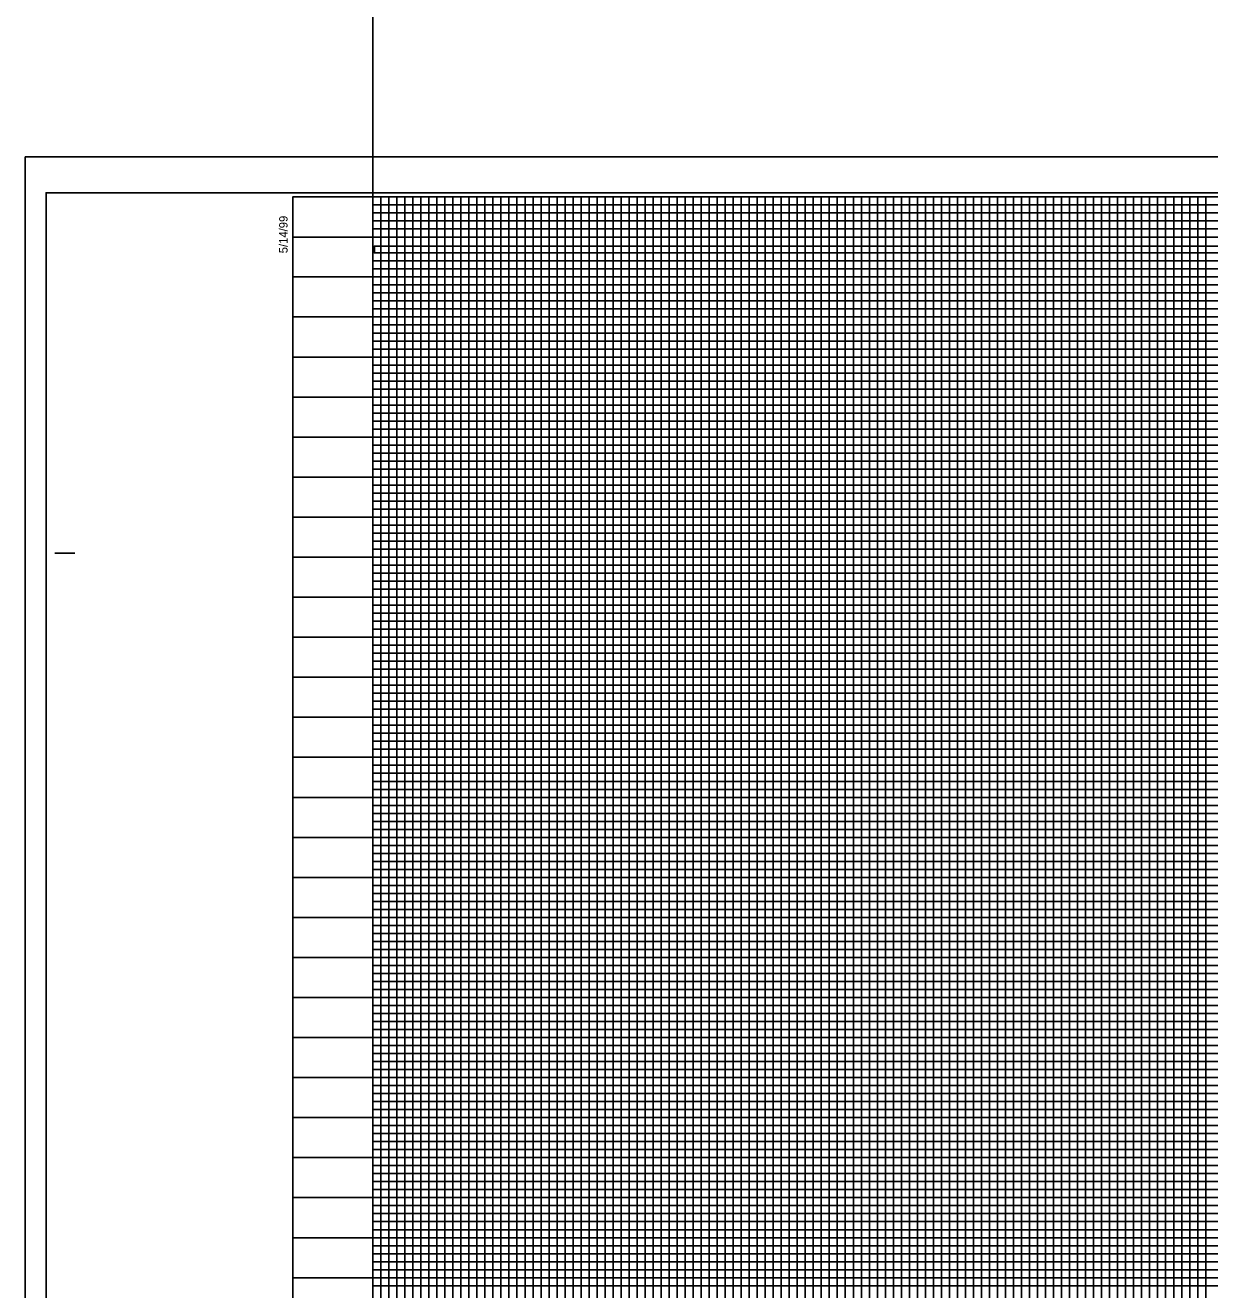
# Model space of a CAD drawing. Extents: x 2345490 to 2445302, y 465165 to 573888.
# Drawn here: x 2381550 to 2382289, y 510797 to 511587 of the extents above; entities that cross this region are included whole.
import ezdxf

# ---------------------------------------------------------------- set-up
doc = ezdxf.new("R2010")
doc.units = 0
for name, color, linetype in [('Old_Level_18', 7, 'Continuous'), ('Old_Level_41', 7, 'Continuous'), ('Old_Level_42', 7, 'Continuous'), ('Old_Level_43', 7, 'Continuous'), ('Old_Level_50', 7, 'Continuous'), ('Old_Level_51', 7, 'Continuous'), ('Old_Level_63', 7, 'Continuous')]:
    doc.layers.add(name, color=color, linetype=linetype)

msp = doc.modelspace()

# ---------------------------------------------------------------- linework, layer by layer
at = {"layer": 'Old_Level_18'}
msp.add_lwpolyline([(2383216.79875, 511479.3835), (2381716.79875, 511479.3835), (2381716.79875, 510429.3835), (2383216.79875, 510429.3835)], close=True, dxfattribs=at)
at = {"layer": 'Old_Level_41'}
msp.add_line((2381568.29875, 511256.8835), (2381580.79875, 511256.8835), dxfattribs=at)
for points in [[(2381716.79875, 511479.3835), (2381766.79875, 511479.3835), (2381766.79875, 510454.3835)], [(2381791.79875, 510454.3835), (2381791.79875, 511479.3835), (2381841.79875, 511479.3835), (2381841.79875, 510454.3835)], [(2381816.79875, 510454.3835), (2381816.79875, 511479.3835), (2381866.79875, 511479.3835), (2381866.79875, 510454.3835)], [(2381891.79875, 510454.3835), (2381891.79875, 511479.3835), (2381941.79875, 511479.3835), (2381941.79875, 510454.3835)], [(2381916.79875, 510454.3835), (2381916.79875, 511479.3835), (2381966.79875, 511479.3835), (2381966.79875, 510454.3835)], [(2381991.79875, 510454.3835), (2381991.79875, 511479.3835), (2382041.79875, 511479.3835), (2382041.79875, 510454.3835)], [(2382016.79875, 510454.3835), (2382016.79875, 511479.3835), (2382066.79875, 511479.3835), (2382066.79875, 510454.3835)], [(2382091.79875, 510454.3835), (2382091.79875, 511479.3835), (2382141.79875, 511479.3835), (2382141.79875, 510454.3835)], [(2382116.79875, 510454.3835), (2382116.79875, 511479.3835), (2382166.79875, 511479.3835), (2382166.79875, 510454.3835)], [(2382191.79875, 510454.3835), (2382191.79875, 511479.3835), (2382241.79875, 511479.3835), (2382241.79875, 510454.3835)], [(2382216.79875, 510454.3835), (2382216.79875, 511479.3835), (2382266.79875, 511479.3835), (2382266.79875, 510454.3835)], [(2381716.79875, 511429.3835), (2383016.74875, 511429.3835)], [(2383016.74875, 511379.3835), (2381716.79875, 511379.3835), (2381716.79875, 511329.3335), (2383216.79875, 511329.3335)], [(2383216.79875, 511304.3835), (2381716.79875, 511304.3835), (2381716.79875, 511354.3835), (2383016.74875, 511354.3835)], [(2383216.79875, 511279.3835), (2381716.79875, 511279.3835), (2381716.79875, 511229.3835), (2383216.79875, 511229.3835)], [(2383216.79875, 511204.3835), (2381716.79875, 511204.3835), (2381716.79875, 511254.3835), (2383216.79875, 511254.3835)], [(2383216.79875, 511179.3835), (2381716.79875, 511179.3835), (2381716.79875, 511129.3835), (2383216.79875, 511129.3835)], [(2383216.79875, 511079.3835), (2381716.79875, 511079.3835), (2381716.79875, 511029.3835), (2383216.79875, 511029.3835)], [(2383216.79875, 510979.3835), (2381716.79875, 510979.3835), (2381716.79875, 510929.3835), (2383216.79875, 510929.3835)], [(2383216.79875, 510879.3835), (2381716.79875, 510879.3835), (2381716.79875, 510829.3835), (2383216.79875, 510829.3835)], [(2383216.79875, 510804.3835), (2381716.79875, 510804.3835), (2381716.79875, 510854.3835), (2383216.79875, 510854.3835)]]:
    msp.add_lwpolyline(points, dxfattribs=at)
at = {"layer": 'Old_Level_42'}
for points in [[(2383016.74875, 511404.3835), (2381716.89875, 511404.3835), (2381716.89875, 511454.3335), (2383016.74875, 511454.3335)], [(2383216.79875, 511104.3835), (2381716.79875, 511104.3835), (2381716.79875, 511154.3835), (2383216.79875, 511154.3835)], [(2383216.79875, 511004.3835), (2381716.79875, 511004.3835), (2381716.79875, 511054.3835), (2383216.79875, 511054.3835)], [(2383216.79875, 510904.3835), (2381716.79875, 510904.3835), (2381716.79875, 510954.3835), (2383216.79875, 510954.3835)]]:
    msp.add_lwpolyline(points, dxfattribs=at)
at = {"layer": 'Old_Level_43'}
for p, q in [((2383166.79875, 511299.3835), (2381766.79875, 511299.3835)), ((2381766.79875, 511299.3835), (2381766.79875, 511294.3835)), ((2381766.79875, 511294.3835), (2383166.79875, 511294.3835)), ((2383166.79875, 511274.3835), (2381766.79875, 511274.3835))]:
    msp.add_line(p, q, dxfattribs=at)
for points in [[(2381771.79875, 511479.3835), (2381776.79875, 511479.3835), (2381781.79875, 511479.3835), (2381786.79875, 511479.3835), (2381796.79875, 511479.3835), (2381763.74875, 511479.3835), (2381768.74875, 511479.3835), (2381726.79875, 511479.3835), (2381731.79875, 511479.3835), (2381736.79875, 511479.3835), (2381746.79875, 511479.3835), (2381751.79875, 511479.3835), (2381756.79875, 511479.3835), (2381761.79875, 511479.3835), (2381771.79875, 511479.3835), (2381771.79875, 510454.3835)], [(2381776.79875, 510454.3835), (2381776.79875, 511479.3835), (2381781.79875, 511479.3835), (2381781.79875, 510454.3835)], [(2381786.79875, 510454.3835), (2381786.79875, 511479.3835), (2381796.79875, 511479.3835), (2381796.79875, 510454.3835)], [(2381801.79875, 510454.3835), (2381801.79875, 511479.3835), (2381806.79875, 511479.3835), (2381806.79875, 510454.3835)], [(2381811.79875, 510454.3835), (2381811.79875, 511479.3835), (2381821.79875, 511479.3835), (2381821.79875, 510454.3835)], [(2381826.79875, 510454.3835), (2381826.79875, 511479.3835), (2381831.79875, 511479.3835), (2381831.79875, 510454.3835)], [(2381836.79875, 510454.3835), (2381836.79875, 511479.3835), (2381846.79875, 511479.3835), (2381846.79875, 510454.3835)], [(2381851.79875, 510454.3835), (2381851.79875, 511479.3835), (2381856.79875, 511479.3835), (2381856.79875, 510454.3835)], [(2381861.79875, 510454.3835), (2381861.79875, 511479.3835), (2381871.79875, 511479.3835), (2381871.79875, 510454.3835)], [(2381876.79875, 510454.3835), (2381876.79875, 511479.3835), (2381881.79875, 511479.3835), (2381881.79875, 510454.3835)], [(2381886.79875, 510454.3835), (2381886.79875, 511479.3835), (2381896.79875, 511479.3835), (2381896.79875, 510454.3835)], [(2381901.79875, 510454.3835), (2381901.79875, 511479.3835), (2381906.79875, 511479.3835), (2381906.79875, 510454.3835)], [(2381911.79875, 510454.3835), (2381911.79875, 511479.3835), (2381921.79875, 511479.3835), (2381921.79875, 510454.3835)], [(2381926.79875, 510454.3835), (2381926.79875, 511479.3835), (2381931.79875, 511479.3835), (2381931.79875, 510454.3835)], [(2381936.79875, 510454.3835), (2381936.79875, 511479.3835), (2381946.79875, 511479.3835), (2381946.79875, 510454.3835)], [(2381951.79875, 510454.3835), (2381951.79875, 511479.3835), (2381956.79875, 511479.3835), (2381956.79875, 510454.3835)], [(2381961.79875, 510454.3835), (2381961.79875, 511479.3835), (2381971.79875, 511479.3835), (2381971.79875, 510454.3835)], [(2381976.79875, 510454.3835), (2381976.79875, 511479.3835), (2381976.79875, 511479.3835), (2381981.79875, 511479.3835), (2381981.79875, 510454.3835)], [(2381986.79875, 510454.3835), (2381986.79875, 511479.3835), (2381996.79875, 511479.3835), (2381996.79875, 510454.3835)], [(2382001.79875, 510454.3835), (2382001.79875, 511479.3835), (2382006.79875, 511479.3835), (2382006.79875, 510454.3835)], [(2382011.79875, 510454.3835), (2382011.79875, 511479.3835), (2382021.79875, 511479.3835), (2382021.79875, 510454.3835)], [(2382026.79875, 510454.3835), (2382026.79875, 511479.3835), (2382031.79875, 511479.3835), (2382031.79875, 510454.3835)], [(2382036.79875, 510454.3835), (2382036.79875, 511479.3835), (2382046.79875, 511479.3835), (2382046.79875, 510454.3835)], [(2382051.79875, 510454.3835), (2382051.79875, 511479.3835), (2382056.79875, 511479.3835), (2382056.79875, 510454.3835)], [(2382061.79875, 510454.3835), (2382061.79875, 511479.3835), (2382071.79875, 511479.3835), (2382071.79875, 510454.3835)], [(2382076.79875, 510454.3835), (2382076.79875, 511479.3835), (2382081.79875, 511479.3835), (2382081.79875, 510454.3835)], [(2382086.79875, 510454.3835), (2382086.79875, 511479.3835), (2382096.79875, 511479.3835), (2382096.79875, 510454.3835)], [(2382101.79875, 511479.3835), (2382101.79875, 510454.3835), (2382106.79875, 510454.3835), (2382106.79875, 511479.3835)], [(2382101.79875, 511478.7835), (2382101.79875, 510454.3835), (2382106.79875, 510454.3835), (2382106.79875, 511478.7835)], [(2382111.79875, 510454.3835), (2382111.79875, 511479.3835), (2382121.79875, 511479.3835), (2382121.79875, 510454.3835)], [(2382126.79875, 510454.3835), (2382126.79875, 511479.3835), (2382131.79875, 511479.3835), (2382131.79875, 510454.3835)], [(2382136.79875, 510454.3835), (2382136.79875, 511479.3835), (2382146.79875, 511479.3835), (2382146.79875, 510454.3835)], [(2382151.79875, 510454.3835), (2382151.79875, 511479.3835), (2382156.79875, 511479.3835), (2382156.79875, 510454.3835)], [(2382161.79875, 510454.3835), (2382161.79875, 511479.3835), (2382171.79875, 511479.3835), (2382171.79875, 510454.3835)], [(2382176.79875, 510454.3835), (2382176.79875, 511479.3835), (2382181.79875, 511479.3835), (2382181.79875, 510454.3835)], [(2382186.79875, 510454.3835), (2382186.79875, 511479.3835), (2382196.79875, 511479.3835), (2382196.79875, 510454.3835)], [(2382201.79875, 510454.3835), (2382201.79875, 511479.3835), (2382206.79875, 511479.3835), (2382206.79875, 510454.3835)], [(2382211.79875, 510454.3835), (2382211.79875, 511479.3835), (2382221.79875, 511479.3835), (2382221.79875, 510454.3835)], [(2382226.79875, 510454.3835), (2382226.79875, 511479.3835), (2382231.79875, 511479.3835), (2382231.79875, 510454.3835)], [(2382236.79875, 510454.3835), (2382236.79875, 511479.3835), (2382246.79875, 511479.3835), (2382246.79875, 510454.3835)], [(2382251.79875, 511479.3835), (2382251.79875, 510454.3835), (2382256.79875, 510454.3835), (2382256.79875, 511479.3835), (2382261.79875, 511479.3835), (2382261.79875, 510454.3835), (2382271.79875, 510454.3835), (2382271.79875, 511479.3835), (2382276.79875, 511479.3835), (2382276.79875, 510454.3835), (2382281.79875, 510454.3835), (2382281.79875, 511479.3835), (2382286.79875, 511479.3835), (2382286.79875, 510454.3835)], [(2383016.74875, 511474.3835), (2381766.79875, 511474.3835), (2381766.79875, 511469.3835), (2383016.74875, 511469.3835)], [(2383016.74875, 511464.3835), (2381766.79875, 511464.3835), (2381766.79875, 511459.3835), (2383016.74875, 511459.3835)], [(2383016.74875, 511448.6335), (2381767.79875, 511448.6335), (2381767.79875, 511444.3835), (2383016.74875, 511444.3835)], [(2383016.74875, 511439.3835), (2381766.79875, 511439.3835), (2381766.79875, 511434.3835), (2383016.74875, 511434.3835)], [(2383016.74875, 511424.3835), (2381766.79875, 511424.3835), (2381766.79875, 511419.3835), (2383016.74875, 511419.3835)], [(2383016.74875, 511414.3835), (2381766.79875, 511414.3835), (2381766.79875, 511409.3835), (2383016.74875, 511409.3835)], [(2383016.74875, 511399.3835), (2381766.79875, 511399.3835), (2381766.79875, 511394.3835), (2383016.74875, 511394.3835)], [(2383016.74875, 511389.3835), (2381766.79875, 511389.3835), (2381766.79875, 511384.3835), (2383016.74875, 511384.3835)], [(2383016.74875, 511374.3835), (2381766.79875, 511374.3835), (2381766.79875, 511369.3835), (2383016.74875, 511369.3835)], [(2383016.74875, 511364.3835), (2381766.79875, 511364.3835), (2381766.79875, 511359.3835), (2383016.74875, 511359.3835)], [(2383016.74875, 511349.3835), (2381766.79875, 511349.3835), (2381766.79875, 511344.3835), (2383016.74875, 511344.3835)], [(2383166.79875, 511339.3835), (2381766.79875, 511339.3835), (2381766.79875, 511339.3835), (2381766.79875, 511319.3835), (2383166.79875, 511319.3835)], [(2381766.79875, 511334.3835), (2383166.79875, 511334.3835)], [(2383166.79875, 511324.3835), (2381766.79875, 511324.3835)], [(2383166.79875, 511314.3835), (2381766.79875, 511314.3835), (2381766.79875, 511309.3835), (2383166.79875, 511309.3835)], [(2383166.79875, 511289.3835), (2381766.79875, 511289.3835), (2381766.79875, 511284.3835), (2383166.79875, 511284.3835)], [(2383166.79875, 511269.3835), (2381766.79875, 511269.3835), (2381766.79875, 511264.3835), (2383166.79875, 511264.3835)], [(2383166.79875, 511259.3835), (2381766.79875, 511259.3835)], [(2381766.79875, 511249.3835), (2383166.79875, 511249.3835)], [(2383166.79875, 511244.3835), (2381766.79875, 511244.3835), (2381766.79875, 511239.3835), (2383166.79875, 511239.3835)], [(2383166.79875, 511234.3835), (2381766.79875, 511234.3835), (2381766.79875, 511224.3835), (2383166.79875, 511224.3835)], [(2383166.79875, 511219.3835), (2381766.79875, 511219.3835), (2381766.79875, 511214.3835), (2383166.79875, 511214.3835)], [(2383166.79875, 511209.3835), (2381766.79875, 511209.3835), (2381766.79875, 511199.3835), (2383166.79875, 511199.3835)], [(2383166.79875, 511194.3835), (2381766.79875, 511194.3835), (2381766.79875, 511189.3835), (2383166.79875, 511189.3835)], [(2383166.79875, 511184.3835), (2381766.79875, 511184.3835), (2381766.79875, 511174.3835), (2383166.79875, 511174.3835)], [(2383166.79875, 511169.3835), (2381766.79875, 511169.3835), (2381766.79875, 511164.3835), (2383166.79875, 511164.3835)], [(2383166.79875, 511159.3835), (2381766.79875, 511159.3835), (2381766.79875, 511149.3835), (2383166.79875, 511149.3835)], [(2383166.79875, 511144.3835), (2381766.79875, 511144.3835), (2381766.79875, 511139.3835), (2383166.79875, 511139.3835)], [(2383166.79875, 511134.3835), (2381766.79875, 511134.3835), (2381766.79875, 511124.3835), (2383166.79875, 511124.3835)], [(2383166.79875, 511119.3835), (2381766.79875, 511119.3835), (2381766.79875, 511114.3835), (2383166.79875, 511114.3835)], [(2383166.79875, 511109.3835), (2381766.79875, 511109.3835), (2381766.79875, 511099.3835), (2383166.79875, 511099.3835)], [(2383166.79875, 511094.3835), (2381766.79875, 511094.3835), (2381766.79875, 511089.3835), (2383166.79875, 511089.3835)], [(2383166.79875, 511084.3835), (2381766.79875, 511084.3835), (2381766.79875, 511074.3835), (2383166.79875, 511074.3835)], [(2383166.79875, 511069.3835), (2381766.79875, 511069.3835), (2381766.79875, 511064.3835), (2383166.79875, 511064.3835)], [(2383166.79875, 511059.3835), (2381766.79875, 511059.3835), (2381766.79875, 511049.3835), (2383166.79875, 511049.3835)], [(2383166.79875, 511044.3835), (2381766.79875, 511044.3835), (2381766.79875, 511039.3835), (2383166.79875, 511039.3835)], [(2383166.79875, 511034.3835), (2381766.79875, 511034.3835), (2381766.79875, 511024.3835), (2383166.79875, 511024.3835)], [(2383166.79875, 511019.3835), (2381766.79875, 511019.3835), (2381766.79875, 511014.3835), (2383166.79875, 511014.3835)], [(2383166.79875, 511009.3835), (2381766.79875, 511009.3835), (2381766.79875, 510999.3835), (2383166.79875, 510999.3835)], [(2383166.79875, 510994.3835), (2381766.79875, 510994.3835), (2381766.79875, 510989.3835), (2383166.79875, 510989.3835)], [(2383166.79875, 510984.3835), (2381766.79875, 510984.3835), (2381766.79875, 510974.3835), (2383166.79875, 510974.3835)], [(2383166.79875, 510969.3835), (2381766.79875, 510969.3835), (2381766.79875, 510964.3835), (2383166.79875, 510964.3835)], [(2383166.79875, 510959.3835), (2381766.79875, 510959.3835)], [(2381766.79875, 510949.3835), (2383166.79875, 510949.3835)], [(2383166.79875, 510944.3835), (2381766.79875, 510944.3835), (2381766.79875, 510939.3835), (2383166.79875, 510939.3835)], [(2383166.79875, 510934.3835), (2381766.79875, 510934.3835), (2381766.79875, 510924.3835), (2383166.79875, 510924.3835)], [(2383166.79875, 510919.3835), (2381766.79875, 510919.3835), (2381766.79875, 510914.3835), (2383166.79875, 510914.3835)], [(2383166.79875, 510909.3835), (2381766.79875, 510909.3835), (2381766.79875, 510899.3835), (2383166.79875, 510899.3835)], [(2383166.79875, 510894.3835), (2381766.79875, 510894.3835), (2381766.79875, 510889.3835), (2383166.79875, 510889.3835)], [(2383166.79875, 510884.3835), (2381766.79875, 510884.3835), (2381766.79875, 510874.3835), (2383166.79875, 510874.3835)], [(2383166.79875, 510869.3835), (2381766.79875, 510869.3835), (2381766.79875, 510864.3835), (2383166.79875, 510864.3835)], [(2383166.79875, 510859.3835), (2381766.79875, 510859.3835), (2381766.79875, 510849.3835), (2383166.79875, 510849.3835)], [(2383166.79875, 510844.3835), (2381766.79875, 510844.3835), (2381766.79875, 510839.3835), (2383166.79875, 510839.3835)], [(2383166.79875, 510834.3835), (2381766.79875, 510834.3835), (2381766.79875, 510824.3835), (2383166.79875, 510824.3835)], [(2383166.79875, 510819.3835), (2381766.79875, 510819.3835), (2381766.79875, 510814.3835), (2383166.79875, 510814.3835)], [(2383166.79875, 510809.3835), (2381766.79875, 510809.3835), (2381766.79875, 510799.3835), (2383166.79875, 510799.3835)]]:
    msp.add_lwpolyline(points, dxfattribs=at)
at = {"layer": 'Old_Level_50'}
msp.add_lwpolyline([(2383229.29875, 511481.9335), (2381562.79875, 511481.9335), (2381562.79875, 510426.8335), (2383229.29875, 510426.8335)], close=True, dxfattribs=at)
at = {"layer": 'Old_Level_51'}
msp.add_lwpolyline([(2383233.79875, 511504.3835), (2381549.79875, 511504.3835), (2381549.79875, 510404.3835), (2383233.79875, 510404.3835)], close=True, dxfattribs=at)
at = {"layer": 'Old_Level_63'}
msp.add_line((2381766.799, 510404.3835), (2381766.799, 512904.3835), dxfattribs=at)

# ---------------------------------------------------------------- texts
at = {"layer": 'Old_Level_41'}
msp.add_text('5/14/99', height=5.25, rotation=90, dxfattribs=at).set_placement((2381713.54875, 511444.1835))

doc.saveas('drawing.dxf')
